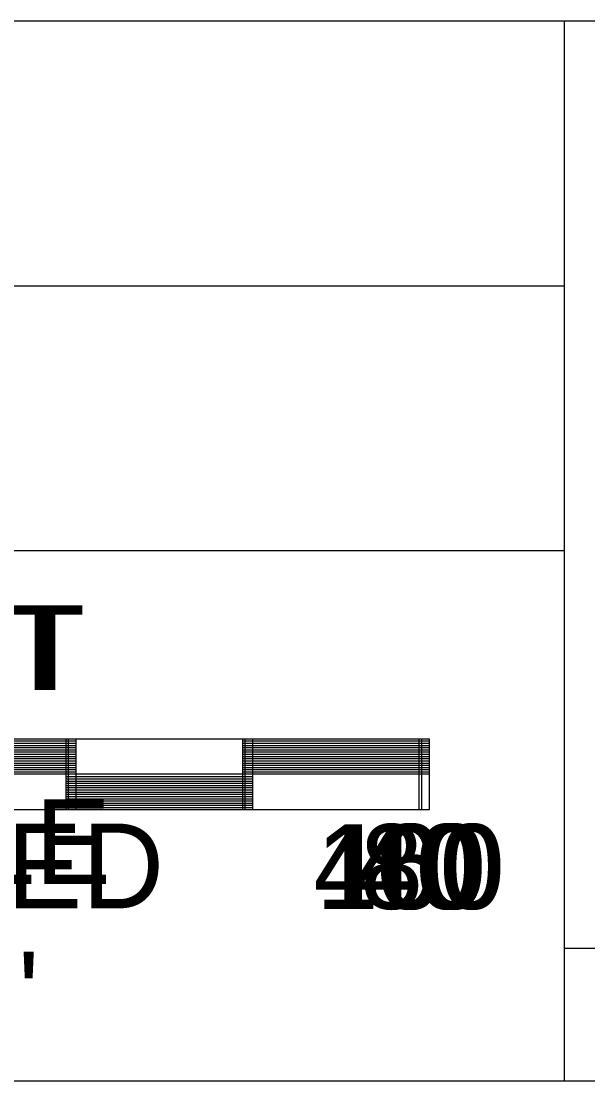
# Model space of a CAD drawing. Extents: x 0 to 2011, y -22 to 1183.
# Drawn here: x 405.2 to 437.3, y -1 to 59 of the extents above; entities that cross this region are included whole.
import ezdxf

# ---------------------------------------------------------------- set-up
doc = ezdxf.new("R2010")
doc.units = 0
for name, color, linetype in [('CT_Border_Perimeter_Shape', 7, 'Continuous'), ('CT_Scale_1_Inch_Equals_200_Feet', 7, 'Continuous'), ('CT_Scale_1_Inch_Equals_20_Feet', 7, 'Continuous'), ('CT_Scale_1_Inch_Equals_40_Feet', 7, 'Continuous'), ('CT_Scale_1_Inch_Equals_80_Feet', 7, 'Continuous'), ('CT_Scale_as_Noted', 7, 'Continuous'), ('CT_Title_Block_Linework', 7, 'Continuous')]:
    doc.layers.add(name, color=color, linetype=linetype)

msp = doc.modelspace()

# ---------------------------------------------------------------- linework, layer by layer
at = {"layer": 'CT_Border_Perimeter_Shape'}
msp.add_lwpolyline([(0, -0.973), (1270, -0.973), (1270, 829.027), (0, 829.027)], close=True, dxfattribs=at)
at = {"layer": 'CT_Scale_1_Inch_Equals_200_Feet'}
for p, q in [((427.743, 18.378), (347.743, 18.378)), ((407.743, 18.254), (397.743, 18.254)), ((407.743, 18.13), (397.743, 18.13)), ((407.743, 18.002), (397.743, 18.002)), ((407.743, 14.388), (407.743, 18.378)), ((417.743, 14.389), (417.743, 18.378)), ((427.743, 18.254), (417.743, 18.254)), ((427.743, 18.13), (417.743, 18.13)), ((427.743, 18.002), (417.743, 18.002)), ((427.743, 14.39), (427.743, 18.378)), ((407.743, 17.878), (397.743, 17.878)), ((407.743, 17.754), (397.743, 17.754)), ((407.743, 17.63), (397.743, 17.63)), ((407.743, 17.502), (397.743, 17.502)), ((427.743, 17.878), (417.743, 17.878)), ((427.743, 17.878), (417.743, 17.878)), ((427.743, 17.754), (417.743, 17.754)), ((427.743, 17.63), (417.743, 17.63)), ((427.743, 17.502), (417.743, 17.502)), ((407.743, 17.378), (397.743, 17.378)), ((407.743, 17.254), (397.743, 17.254)), ((407.743, 17.13), (397.743, 17.13)), ((407.743, 17.002), (397.743, 17.002)), ((407.743, 16.878), (397.743, 16.878)), ((427.743, 17.378), (417.743, 17.378)), ((427.743, 17.254), (417.743, 17.254)), ((427.743, 17.13), (417.743, 17.13)), ((427.743, 17.002), (417.743, 17.002)), ((427.743, 16.878), (417.743, 16.878)), ((427.743, 16.39), (347.743, 16.364)), ((407.743, 16.754), (397.743, 16.754)), ((407.743, 16.63), (397.743, 16.63)), ((407.743, 16.502), (397.743, 16.502)), ((407.743, 16.254), (417.743, 16.254)), ((427.743, 16.754), (417.743, 16.754)), ((427.743, 16.63), (417.743, 16.63)), ((427.743, 16.502), (417.743, 16.502)), ((407.743, 16.13), (417.743, 16.13)), ((407.743, 16.002), (417.743, 16.002)), ((407.743, 15.878), (417.743, 15.878)), ((407.743, 15.754), (417.743, 15.754)), ((407.743, 15.63), (417.743, 15.63)), ((407.743, 15.502), (417.743, 15.502)), ((407.743, 15.378), (417.743, 15.378)), ((407.743, 15.254), (417.743, 15.254)), ((407.743, 15.13), (417.743, 15.13)), ((407.743, 15.002), (417.743, 15.002)), ((407.743, 14.878), (417.743, 14.878)), ((407.743, 14.754), (417.743, 14.754)), ((407.743, 14.63), (417.743, 14.63)), ((407.743, 14.502), (417.743, 14.502)), ((347.743, 14.384), (427.743, 14.39))]:
    msp.add_line(p, q, dxfattribs=at)
at = {"layer": 'CT_Scale_1_Inch_Equals_20_Feet'}
for p, q in [((427.888, 18.378), (347.888, 18.378)), ((407.888, 18.254), (397.888, 18.254)), ((407.888, 18.13), (397.888, 18.13)), ((407.888, 18.002), (397.888, 18.002)), ((407.888, 14.388), (407.888, 18.378)), ((417.888, 14.389), (417.888, 18.378)), ((427.888, 18.254), (417.888, 18.254)), ((427.888, 18.13), (417.888, 18.13)), ((427.888, 18.002), (417.888, 18.002)), ((427.888, 14.39), (427.888, 18.378)), ((407.888, 17.878), (397.888, 17.878)), ((407.888, 17.754), (397.888, 17.754)), ((407.888, 17.63), (397.888, 17.63)), ((407.888, 17.502), (397.888, 17.502)), ((427.888, 17.878), (417.888, 17.878)), ((427.888, 17.878), (417.888, 17.878)), ((427.888, 17.754), (417.888, 17.754)), ((427.888, 17.63), (417.888, 17.63)), ((427.888, 17.502), (417.888, 17.502)), ((407.888, 17.378), (397.888, 17.378)), ((407.888, 17.254), (397.888, 17.254)), ((407.888, 17.13), (397.888, 17.13)), ((407.888, 17.002), (397.888, 17.002)), ((407.888, 16.878), (397.888, 16.878)), ((427.888, 17.378), (417.888, 17.378)), ((427.888, 17.254), (417.888, 17.254)), ((427.888, 17.13), (417.888, 17.13)), ((427.888, 17.002), (417.888, 17.002)), ((427.888, 16.878), (417.888, 16.878)), ((427.888, 16.39), (347.888, 16.364)), ((407.888, 16.754), (397.888, 16.754)), ((407.888, 16.63), (397.888, 16.63)), ((407.888, 16.502), (397.888, 16.502)), ((407.888, 16.254), (417.888, 16.254)), ((427.888, 16.754), (417.888, 16.754)), ((427.888, 16.63), (417.888, 16.63)), ((427.888, 16.502), (417.888, 16.502)), ((407.888, 16.13), (417.888, 16.13)), ((407.888, 16.002), (417.888, 16.002)), ((407.888, 15.878), (417.888, 15.878)), ((407.888, 15.754), (417.888, 15.754)), ((407.888, 15.63), (417.888, 15.63)), ((407.888, 15.502), (417.888, 15.502)), ((407.888, 15.378), (417.888, 15.378)), ((407.888, 15.254), (417.888, 15.254)), ((407.888, 15.13), (417.888, 15.13)), ((407.888, 15.002), (417.888, 15.002)), ((407.888, 14.878), (417.888, 14.878)), ((407.888, 14.754), (417.888, 14.754)), ((407.888, 14.63), (417.888, 14.63)), ((407.888, 14.502), (417.888, 14.502)), ((347.888, 14.384), (427.888, 14.39))]:
    msp.add_line(p, q, dxfattribs=at)
at = {"layer": 'CT_Scale_1_Inch_Equals_40_Feet'}
for p, q in [((428.32, 18.378), (348.32, 18.378)), ((408.32, 18.254), (398.32, 18.254)), ((408.32, 18.13), (398.32, 18.13)), ((408.32, 18.002), (398.32, 18.002)), ((408.32, 14.388), (408.32, 18.378)), ((418.32, 14.389), (418.32, 18.378)), ((428.32, 18.254), (418.32, 18.254)), ((428.32, 18.13), (418.32, 18.13)), ((428.32, 18.002), (418.32, 18.002)), ((428.32, 14.39), (428.32, 18.378)), ((408.32, 17.878), (398.32, 17.878)), ((408.32, 17.754), (398.32, 17.754)), ((408.32, 17.63), (398.32, 17.63)), ((408.32, 17.502), (398.32, 17.502)), ((428.32, 17.878), (418.32, 17.878)), ((428.32, 17.878), (418.32, 17.878)), ((428.32, 17.754), (418.32, 17.754)), ((428.32, 17.63), (418.32, 17.63)), ((428.32, 17.502), (418.32, 17.502)), ((408.32, 17.378), (398.32, 17.378)), ((408.32, 17.254), (398.32, 17.254)), ((408.32, 17.13), (398.32, 17.13)), ((408.32, 17.002), (398.32, 17.002)), ((408.32, 16.878), (398.32, 16.878)), ((428.32, 17.378), (418.32, 17.378)), ((428.32, 17.254), (418.32, 17.254)), ((428.32, 17.13), (418.32, 17.13)), ((428.32, 17.002), (418.32, 17.002)), ((428.32, 16.878), (418.32, 16.878)), ((428.32, 16.39), (348.32, 16.364)), ((408.32, 16.754), (398.32, 16.754)), ((408.32, 16.63), (398.32, 16.63)), ((408.32, 16.502), (398.32, 16.502)), ((408.32, 16.254), (418.32, 16.254)), ((428.32, 16.754), (418.32, 16.754)), ((428.32, 16.63), (418.32, 16.63)), ((428.32, 16.502), (418.32, 16.502)), ((408.32, 16.13), (418.32, 16.13)), ((408.32, 16.002), (418.32, 16.002)), ((408.32, 15.878), (418.32, 15.878)), ((408.32, 15.754), (418.32, 15.754)), ((408.32, 15.63), (418.32, 15.63)), ((408.32, 15.502), (418.32, 15.502)), ((408.32, 15.378), (418.32, 15.378)), ((408.32, 15.254), (418.32, 15.254)), ((408.32, 15.13), (418.32, 15.13)), ((408.32, 15.002), (418.32, 15.002)), ((408.32, 14.878), (418.32, 14.878)), ((408.32, 14.754), (418.32, 14.754)), ((408.32, 14.63), (418.32, 14.63)), ((408.32, 14.502), (418.32, 14.502)), ((348.32, 14.384), (428.32, 14.39))]:
    msp.add_line(p, q, dxfattribs=at)
at = {"layer": 'CT_Scale_1_Inch_Equals_80_Feet'}
for p, q in [((427.88, 18.378), (347.88, 18.378)), ((407.88, 18.254), (397.88, 18.254)), ((407.88, 18.13), (397.88, 18.13)), ((407.88, 18.002), (397.88, 18.002)), ((407.88, 14.388), (407.88, 18.378)), ((417.88, 14.389), (417.88, 18.378)), ((427.88, 18.254), (417.88, 18.254)), ((427.88, 18.13), (417.88, 18.13)), ((427.88, 18.002), (417.88, 18.002)), ((427.88, 14.39), (427.88, 18.378)), ((407.88, 17.878), (397.88, 17.878)), ((407.88, 17.754), (397.88, 17.754)), ((407.88, 17.63), (397.88, 17.63)), ((407.88, 17.502), (397.88, 17.502)), ((427.88, 17.878), (417.88, 17.878)), ((427.88, 17.878), (417.88, 17.878)), ((427.88, 17.754), (417.88, 17.754)), ((427.88, 17.63), (417.88, 17.63)), ((427.88, 17.502), (417.88, 17.502)), ((407.88, 17.378), (397.88, 17.378)), ((407.88, 17.254), (397.88, 17.254)), ((407.88, 17.13), (397.88, 17.13)), ((407.88, 17.002), (397.88, 17.002)), ((407.88, 16.878), (397.88, 16.878)), ((427.88, 17.378), (417.88, 17.378)), ((427.88, 17.254), (417.88, 17.254)), ((427.88, 17.13), (417.88, 17.13)), ((427.88, 17.002), (417.88, 17.002)), ((427.88, 16.878), (417.88, 16.878)), ((427.88, 16.39), (347.88, 16.364)), ((407.88, 16.754), (397.88, 16.754)), ((407.88, 16.63), (397.88, 16.63)), ((407.88, 16.502), (397.88, 16.502)), ((407.88, 16.254), (417.88, 16.254)), ((427.88, 16.754), (417.88, 16.754)), ((427.88, 16.63), (417.88, 16.63)), ((427.88, 16.502), (417.88, 16.502)), ((407.88, 16.13), (417.88, 16.13)), ((407.88, 16.002), (417.88, 16.002)), ((407.88, 15.878), (417.88, 15.878)), ((407.88, 15.754), (417.88, 15.754)), ((407.88, 15.63), (417.88, 15.63)), ((407.88, 15.502), (417.88, 15.502)), ((407.88, 15.378), (417.88, 15.378)), ((407.88, 15.254), (417.88, 15.254)), ((407.88, 15.13), (417.88, 15.13)), ((407.88, 15.002), (417.88, 15.002)), ((407.88, 14.878), (417.88, 14.878)), ((407.88, 14.754), (417.88, 14.754)), ((407.88, 14.63), (417.88, 14.63)), ((407.88, 14.502), (417.88, 14.502)), ((347.88, 14.384), (427.88, 14.39))]:
    msp.add_line(p, q, dxfattribs=at)
at = {"layer": 'CT_Title_Block_Linework'}
for p, q in [((1270, 59.027), (0, 59.027)), ((435.948, 59.027), (435.948, -0.973)), ((435.948, 44.027), (344.549, 44.027)), ((435.948, 29.027), (344.549, 29.027)), ((651.861, 6.527), (435.948, 6.527))]:
    msp.add_line(p, q, dxfattribs=at)

# ---------------------------------------------------------------- texts
at = {"layer": 'CT_Border_Perimeter_Shape'}
msp.add_text('NOT TO SCALE', height=4.8, dxfattribs=at).set_placement((363.195, 10.172))
at = {"layer": 'CT_Scale_1_Inch_Equals_200_Feet'}
for s, p in [('SCALE IN FEET', (360.792, 21.151)), ('400', (421.741, 8.757))]:
    msp.add_text(s, height=4.8, dxfattribs=at).set_placement(p)
msp.add_text('SCALE 1"=200\'', height=4.8, rotation=0.01259, dxfattribs=at).set_placement((361.876, 1.532))
at = {"layer": 'CT_Scale_1_Inch_Equals_20_Feet'}
for s, p in [('SCALE IN FEET', (360.938, 21.151)), ('40', (423.96, 8.757))]:
    msp.add_text(s, height=4.8, dxfattribs=at).set_placement(p)
at = {"layer": 'CT_Scale_1_Inch_Equals_40_Feet'}
for s, p in [('SCALE IN FEET', (361.369, 21.151)), ('80', (424.391, 8.757))]:
    msp.add_text(s, height=4.8, rotation=360, dxfattribs=at).set_placement(p)
at = {"layer": 'CT_Scale_1_Inch_Equals_80_Feet'}
for s, p in [('SCALE IN FEET', (360.929, 21.151)), ('160', (421.879, 8.757))]:
    msp.add_text(s, height=4.8, dxfattribs=at).set_placement(p)
at = {"layer": 'CT_Scale_as_Noted'}
msp.add_text('SCALE AS NOTED', height=4.8, dxfattribs=at).set_placement((357.647, 8.796))

doc.saveas('drawing.dxf')
